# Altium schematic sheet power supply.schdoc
size 235 x 107 mm
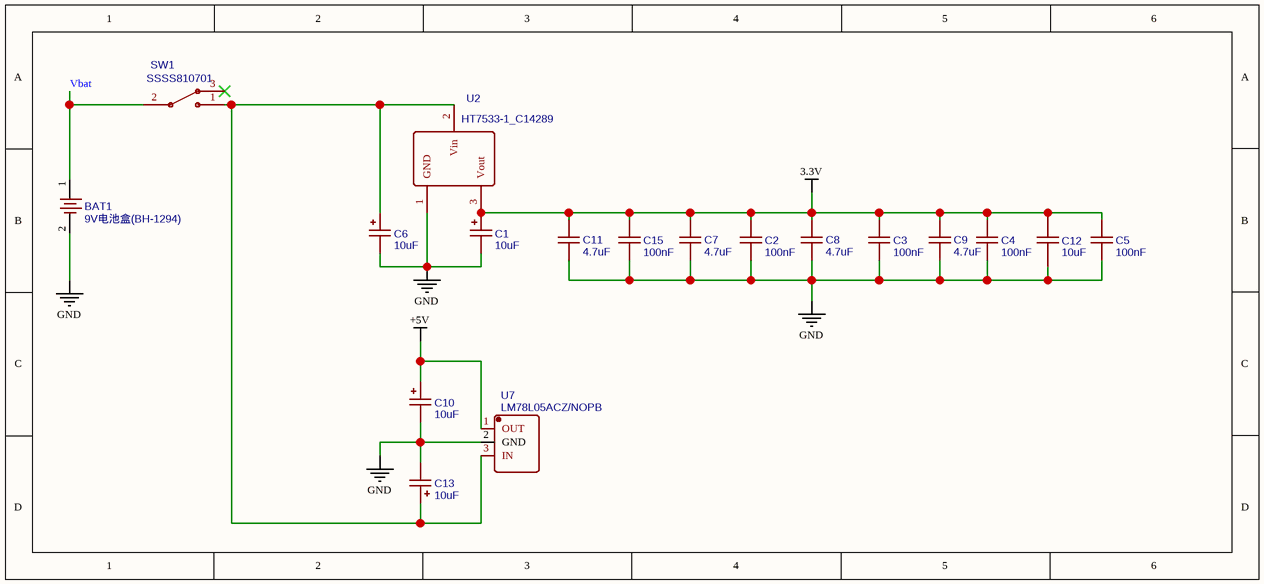
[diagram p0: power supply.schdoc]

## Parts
BAT1  9V电池盒(BH-1294)  [BAT-TH_BH-1294]
C1  10uF  [CAP-SMD_L3.2-W1.6-RD-C7171]
C2  100nF  [C1206]
C3  100nF  [C1206]
C4  100nF  [C1206]
C5  100nF  [C1206]
C6  10uF  [CAP-SMD_L3.2-W1.6-RD-C7171]
C7  4.7uF  [C1206]
C8  4.7uF  [C1206]
C9  4.7uF  [C1206]
C10  10uF  [CAP-SMD_L3.2-W1.6-RD-C7171]
C11  4.7uF  [C1206]
C12  10uF  [C0603]
C13  10uF  [CAP-SMD_L3.2-W1.6-RD-C7171]
C15  100nF  [C1206]
SW1  SSSS810701  [SW-SMD_SSSS810701]
U2  HT7533-1_C14289  [SOT-89-3_L4.5-W2.5-P1.50-LS4.2-BR]
U7  LM78L05ACZ/NOPB  [TO-92-3_L4.9-W3.7-P1.27-L]

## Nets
3.3V: C1.1 C2.2 C3.2 C4.2 C5.2 C7.1 C8.1 C9.1 C11.1 C12.2 C15.2 U2.3(Vout)
+5V: C10.1 U7.1(OUT)
GND: BAT1.2 C1.2 C2.1 C3.1 C4.1 C5.1 C6.2 C7.2 C8.2 C9.2 C10.2 C11.2 C12.1 C13.2 C15.1 U2.1(GND) U7.2(GND)
Vbat: BAT1.1 SW1.2
NetC6_1: C6.1 C13.1 SW1.1 U2.2(Vin) U7.3(IN)

Not connected (* = marked no-connect by the designer): SW1 3*

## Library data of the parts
BAT1 = 9V电池盒(BH-1294): Manufacturer: null; Contributor: LCSC
C1 C6 C10 C13 = 10uF: Manufacturer: Kyocera AVX; Manufacturer Part: TAJA106K016RNJ; nameAlias: Value
C2-C5 C15 = 100nF: Manufacturer Part: CL31B104KBCNNNC; Manufacturer: SAMSUNG(三星); nameAlias: Value
C7-C9 C11 = 4.7uF: Manufacturer: FH(风华); Manufacturer Part: 1206B475K500NT; nameAlias: Value
C12 = 10uF: Manufacturer: SAMSUNG(三星); Manufacturer Part: CL10A106MA8NRNC; nameAlias: Value
SW1 = SSSS810701: Manufacturer: ALPSALPINE(阿尔卑斯阿尔派); Contributor: LCSC
U2 = HT7533-1_C14289: Manufacturer: HOLTEK(合泰/盛群)
U7 = LM78L05ACZ/NOPB: Manufacturer: TI(德州仪器)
